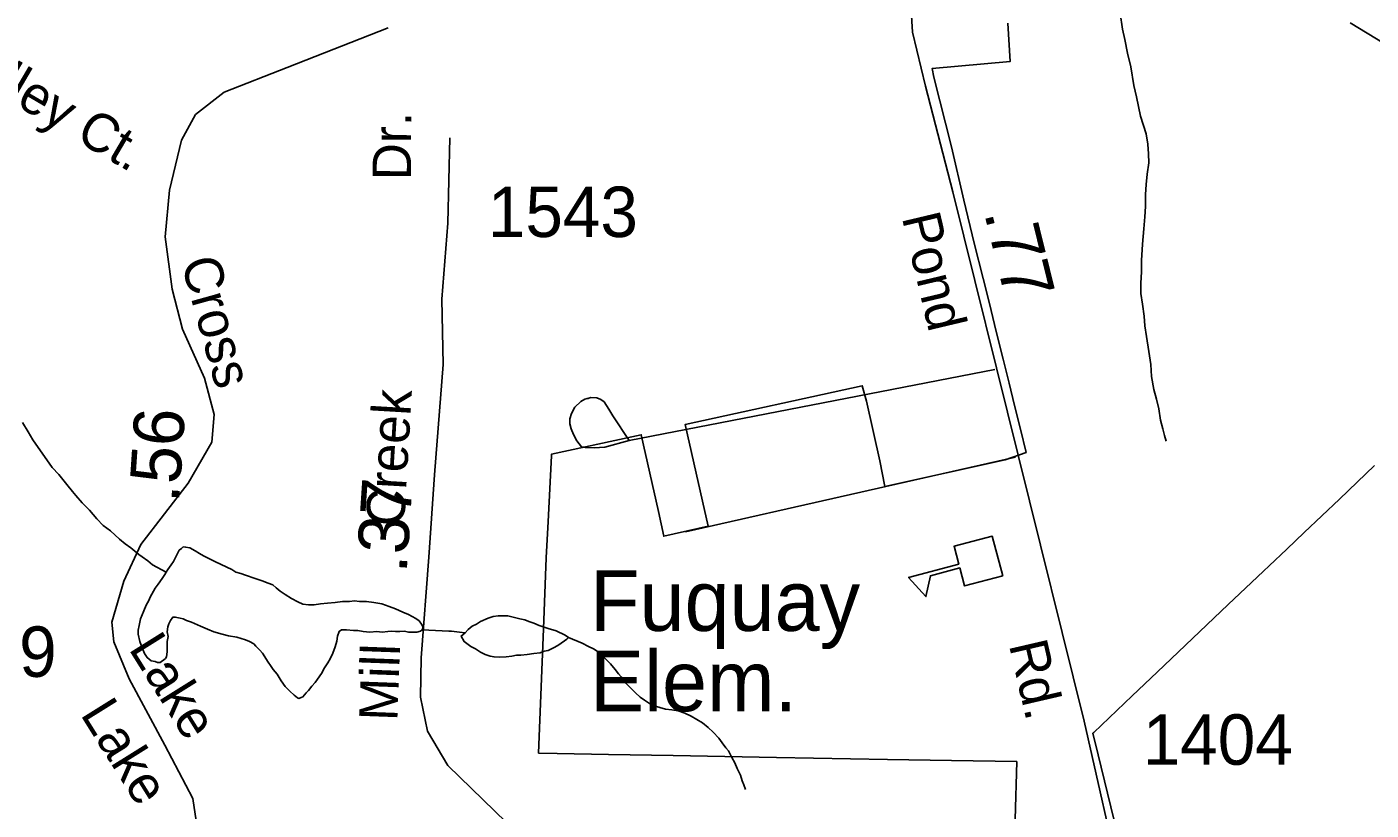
# Model space of a CAD drawing. Extents: x 2001466 to 2224147, y 644118 to 847247.
# Drawn here: x 2069996 to 2073326, y 673987 to 675928 of the extents above; entities that cross this region are included whole.
import ezdxf

# ---------------------------------------------------------------- set-up
doc = ezdxf.new("R2010")
doc.units = 0
for name, color, linetype in [('Exist Boundary Political City Limit New', 7, 'Continuous'), ('Exist Cultural Educational Facility Elementary CELL', 7, 'Continuous'), ('Exist Cultural Educational Facility Elementary Label', 7, 'Continuous'), ('Exist Hydrographic Misc Water Feature', 7, 'Continuous'), ('Exist Road Non-System Type 51', 7, 'Continuous'), ('Exist Road Non-System Type 51 Label', 7, 'Continuous'), ('Exist Road Secondary Mileage Hundredths English Label', 7, 'Continuous'), ('Exist Road Secondary Type 51 Attributed', 7, 'Continuous'), ('Exist Road Secondary Type 51 Label', 7, 'Continuous'), ('Exist Road Secondary Type 51 Number Label', 7, 'Continuous'), ('Map Preparation Boundary City Limit Buffer Line', 7, 'Continuous')]:
    doc.layers.add(name, color=color, linetype=linetype)

msp = doc.modelspace()

# ---------------------------------------------------------------- linework, layer by layer
at = {"layer": 'Exist Boundary Political City Limit New'}
for points in [[(2072426.2, 675937.6), (2072431.8, 675842.2), (2072238.5, 675824.8), (2072242.5, 675803.8), (2072286.8, 675631), (2072317, 675498.6), (2072343.1, 675391.9), (2072365, 675304.7), (2072380.5, 675242.3), (2072397.6, 675173.2), (2072414.5, 675104.6), (2072429.2, 675045.1), (2072443, 674989.8), (2072457.5, 674930.9), (2072471.5, 674873.2), (2072419.2, 674855.2), (2072121.8, 674788.9), (2072109, 674852.2), (2072076, 675000), (2072065.4, 675038.4), (2071626.5, 674942.2), (2071669.6, 674752.2), (2071683.6, 674690.2), (2071573.8, 674665.3), (2071560.5, 674727.1), (2071518.2, 674917.2), (2071494.5, 674911.8), (2071296.1, 674869.2), (2071295.9, 674865.1), (2071287.1, 674701.6), (2071282.2, 674612.2), (2071275.5, 674435.9), (2071263.9, 674127.9), (2071309.8, 674127.1), (2071437.2, 674124.7), (2071597, 674121.8), (2071853.5, 674117.1), (2072127.9, 674112.4), (2072286.5, 674109.7)], [(2073419.4, 675849.8), (2073274.6, 675937.8)], [(2073737, 674256.3), (2073303.4, 673844.5), (2073243.2, 673787.3), (2072727.5, 673804.9), (2072649.8, 674123.6), (2072636.9, 674177.1), (2072639, 674179), (2072734.5, 674270.1), (2072796, 674328.8), (2072866.4, 674395.6), (2072972.1, 674496.1), (2073030.1, 674550.9), (2073059.8, 674579.1), (2073073.6, 674592.2), (2073117.1, 674633.6), (2073160.6, 674674.9), (2073204.1, 674716.2), (2073247.6, 674757.5), (2073291.4, 674799.2), (2073334.9, 674840.6)], [(2072286.5, 674109.7), (2072448.1, 674106.9), (2072440.5, 673819.2)]]:
    msp.add_lwpolyline(points, dxfattribs=at)
at = {"layer": 'Exist Cultural Educational Facility Elementary CELL'}
msp.add_lwpolyline([(2072413.6, 674567.3), (2072319, 674542.3), (2072307.2, 674586.8), (2072234.6, 674567.6), (2072223.2, 674516), (2072180.5, 674563.3), (2072304.7, 674596.1), (2072293, 674640.6), (2072387.7, 674665.6)], close=True, dxfattribs=at)
at = {"layer": 'Exist Hydrographic Misc Water Feature'}
for points in [[(2072818.2, 674901.3), (2072814.3, 674915.2), (2072810, 674931.3), (2072804.5, 674953.2), (2072800.6, 674981), (2072794.4, 675005.1), (2072788.1, 675029.1), (2072782.1, 675061.2), (2072780.3, 675091.1), (2072775.8, 675123.1), (2072769.8, 675160.9), (2072765.9, 675187), (2072764.1, 675210.8), (2072759.8, 675241.1), (2072755.9, 675266.8), (2072755.7, 675293.2), (2072757.7, 675320.9), (2072757.3, 675348.9), (2072759.8, 675389.1), (2072763.4, 675427.1), (2072765.5, 675457.2), (2072767.3, 675482.9), (2072767.1, 675512.9), (2072769, 675537), (2072771.2, 675563), (2072775.1, 675590.8), (2072774.9, 675613.1), (2072773.1, 675637), (2072768.8, 675663.1), (2072754.8, 675707), (2072744.6, 675754.8), (2072738.6, 675782.9), (2072730.6, 675828.8), (2072722.6, 675862.8), (2072716.3, 675896.6), (2072710.5, 675922.6), (2072704.4, 675962.5)], [(2070341.4, 674576.6), (2070307.3, 674594.7), (2070295.4, 674604.6), (2070281.3, 674614.4), (2070273.5, 674620.5), (2070253.6, 674636.5), (2070239.5, 674646.4), (2070225.3, 674658.2), (2070203.2, 674678.6), (2070185.1, 674692.3), (2070169.5, 674708.5), (2070151.1, 674730.3), (2070133.2, 674748), (2070117, 674766.3), (2070109.5, 674776), (2070094.9, 674794), (2070075.2, 674818.1), (2070059, 674835.9), (2070010.8, 674904.1), (2069998.9, 674924.2), (2069985, 674947.7)], [(2070341.4, 674576.6), (2070345.5, 674582.9), (2070353.3, 674594.6), (2070359.4, 674602.6), (2070365.2, 674614.7), (2070369.5, 674622.6), (2070373.4, 674630.9), (2070379.1, 674634.9), (2070383.2, 674638.8), (2070389.1, 674638.7), (2070399.4, 674636.7), (2070413.3, 674628.9), (2070423.4, 674622.9), (2070433.6, 674616.9), (2070461.3, 674603), (2070491.5, 674589.1), (2070503.6, 674582.8), (2070513.6, 674576.8), (2070525.7, 674573), (2070537.8, 674569.1), (2070561.6, 674561), (2070579.2, 674555.1), (2070593.6, 674549.3), (2070605.7, 674545), (2070613.7, 674537.3), (2070623.3, 674529.3), (2070635.6, 674521.4), (2070651.4, 674511.3), (2070667.4, 674503.2), (2070679.7, 674497.3), (2070693.4, 674495.2), (2070707.4, 674495.5), (2070723.6, 674497.6), (2070741.2, 674499.3), (2070759.5, 674501.5), (2070777.7, 674503.6), (2070795.6, 674503.7), (2070807.3, 674505.6), (2070819.8, 674503.7), (2070837.6, 674503.8), (2070855.4, 674501.5), (2070875.7, 674497.6), (2070893.4, 674491.7), (2070909.4, 674485.6), (2070927.6, 674477.6), (2070941.6, 674471.8), (2070959.4, 674461.8), (2070967.8, 674455.7), (2070973.8, 674447.9), (2070977.9, 674439.9), (2070975.6, 674433.8)], [(2070975.6, 674433.8), (2070971.5, 674429.9), (2070961.9, 674427.8), (2070941.4, 674428), (2070931.5, 674429.9), (2070919.6, 674429.7), (2070909.4, 674429.6), (2070899.7, 674429.9), (2070889.9, 674429.7), (2070875.9, 674427.8), (2070863.4, 674429.7), (2070845.8, 674427.5), (2070829.4, 674429.6), (2070815.9, 674431.6), (2070805.6, 674431.6), (2070787.6, 674433.5), (2070775.7, 674433.7), (2070769.5, 674429.7), (2070765.4, 674417.4), (2070763.8, 674405.4), (2070759.9, 674391.4), (2070753.7, 674375.3), (2070747.6, 674361.7), (2070741.6, 674351.6), (2070733.6, 674339.5), (2070725.8, 674325.6), (2070715.8, 674311.3), (2070709.9, 674303.3), (2070701.9, 674293.6), (2070693.9, 674283.4), (2070688.1, 674277.4), (2070680.1, 674267.3), (2070675.8, 674265.5), (2070670.1, 674263.5), (2070666.2, 674265.3), (2070658.2, 674271.4), (2070647.9, 674281.5), (2070635.8, 674293.4), (2070625.8, 674307.1), (2070615.7, 674323.3), (2070605.9, 674335.3), (2070599.9, 674345.1), (2070593.6, 674353.4), (2070579.8, 674375.3), (2070573.5, 674383.2), (2070563.6, 674393.2), (2070557.9, 674398.9), (2070547.9, 674404.9), (2070537.8, 674408.9), (2070515.9, 674415), (2070495.8, 674418.9), (2070479.8, 674423), (2070459.5, 674428.9), (2070443.5, 674434.9), (2070425.9, 674442.9), (2070403.7, 674452.8), (2070391.6, 674457), (2070383.6, 674460.6), (2070375.6, 674462.7), (2070363.5, 674464.9), (2070357.6, 674464.6), (2070351.6, 674456.6), (2070347.7, 674448.6), (2070345.5, 674440.9), (2070343.8, 674428.6), (2070345.9, 674416.9), (2070343.8, 674404.6), (2070343.8, 674392.8), (2070343.6, 674378.7), (2070342.2, 674366.7), (2070339.7, 674362.6), (2070335.6, 674358.8), (2070329.9, 674354.8), (2070326.2, 674352.5), (2070319.8, 674352.7), (2070313.7, 674354.8), (2070303.8, 674356.7), (2070293.8, 674364.7), (2070287.6, 674374.6), (2070281.9, 674388.5), (2070275.8, 674404.8), (2070271.9, 674422.4), (2070271.9, 674432.6), (2070273.9, 674444.4), (2070275.8, 674452.6), (2070277.8, 674460.4), (2070281.7, 674470.8), (2070285.4, 674480.8), (2070291.5, 674494.5), (2070297.9, 674506.5), (2070301.8, 674514.4), (2070313.5, 674536.6), (2070321.5, 674546.7), (2070331.5, 674560.6), (2070337.5, 674570.7), (2070341.4, 674576.6)], [(2071081.8, 674426.2), (2071089.4, 674434), (2071099.5, 674442.2), (2071109.7, 674447.9), (2071119.5, 674454.1), (2071139.2, 674462.1), (2071151.3, 674466.4), (2071163.6, 674468.2), (2071179.4, 674468.2), (2071187.4, 674468.2), (2071217.6, 674460.4), (2071229.5, 674458.2), (2071239.5, 674454.2), (2071251.6, 674450.4), (2071265.5, 674444.2), (2071277.6, 674440.3), (2071287.5, 674436.4), (2071307.4, 674430.6), (2071329.5, 674420.3), (2071337.5, 674414.7)], [(2071081.8, 674426.2), (2071067.7, 674427.9), (2071047.6, 674430.2), (2071041.6, 674429.9), (2070975.6, 674433.8)], [(2071337.5, 674414.7), (2071333.4, 674410.4), (2071313.5, 674396.4), (2071303.7, 674390.6), (2071295.9, 674386.5), (2071287.5, 674382.5), (2071277.8, 674380.3), (2071267.8, 674376.5), (2071251.8, 674374.5), (2071235.6, 674372.5), (2071219.6, 674370.5), (2071209.4, 674370.4), (2071197.7, 674368.5), (2071183.5, 674366.2), (2071167.9, 674366.1), (2071153.4, 674366.3), (2071143.5, 674368.2), (2071131.4, 674372.1), (2071119.8, 674377.9), (2071107.4, 674386.2), (2071095.8, 674392.1), (2071079.4, 674404.3), (2071071.6, 674418), (2071081.8, 674426.2)], [(2071776.1, 674037.5), (2071772.2, 674049.4), (2071767.9, 674059.4), (2071763.8, 674073.4), (2071756, 674089.6), (2071750.1, 674103.4), (2071742.3, 674117.2), (2071733.9, 674133.5), (2071727.9, 674141.3), (2071718.1, 674153.3), (2071709.9, 674165.1), (2071696.2, 674179.4), (2071684.1, 674191.4), (2071669.9, 674203.3), (2071656, 674211), (2071642, 674219.2), (2071625.8, 674226.9), (2071609.8, 674233), (2071594, 674235), (2071577.8, 674237.1), (2071564.1, 674241.2), (2071549.7, 674245), (2071538.1, 674250.8), (2071525.8, 674259.1), (2071515.5, 674266.8), (2071503.6, 674277.1), (2071489.9, 674291), (2071480, 674301), (2071467.9, 674317), (2071462, 674324.8), (2071453.4, 674335), (2071441.7, 674348.9), (2071427.5, 674362.9), (2071419.3, 674370.6), (2071411.3, 674378.7), (2071399.4, 674386.6), (2071387.3, 674392.5), (2071371.8, 674400.5), (2071337.5, 674414.7)]]:
    msp.add_lwpolyline(points, dxfattribs=at)
at = {"layer": 'Exist Road Non-System Type 51'}
for p, q in [((2072393.7, 675078.7), (2071488.1, 674903.1)), ((2072445.3, 674861.6), (2071627.5, 674676.2))]:
    msp.add_line(p, q, dxfattribs=at)
msp.add_lwpolyline([(2071488.1, 674903.1), (2071427.8, 674886.3), (2071401.8, 674884.8), (2071385.8, 674885.2), (2071379.8, 674885.3), (2071369.8, 674887.5), (2071358.1, 674901.7), (2071350.4, 674917.9), (2071344.7, 674932), (2071341, 674944.1), (2071341.2, 674956.1), (2071345.5, 674970), (2071353.8, 674985.8), (2071368.1, 674999.5), (2071378.2, 675005.3), (2071384.2, 675007.2), (2071386.2, 675007.1), (2071392.3, 675009), (2071408.3, 675008.7), (2071418.2, 675004.5), (2071426.1, 674998.3), (2071437.7, 674980.1), (2071447.4, 674963.9), (2071488.1, 674903.1)], dxfattribs=at)
at = {"layer": 'Exist Road Secondary Type 51 Attributed'}
for points in [[(2072367.4, 677776.1), (2072362.4, 677627.2), (2072394, 677399), (2072419.2, 677268), (2072420.8, 677193.7), (2072412.9, 677071.4), (2072376.6, 676885), (2072308.8, 676591.3), (2072253.5, 676367.9), (2072209.3, 676153.1), (2072184.1, 676011), (2072190.4, 675914.7), (2072222, 675781.3), (2072289.8, 675519.2), (2072614.9, 674207), (2072710.3, 673786.9)], [(2070415.2, 673959.8), (2070407.3, 674015.1), (2070337.9, 674147.7), (2070249.5, 674312), (2070211.7, 674403.6), (2070206.9, 674452.5), (2070236.1, 674554), (2070278.7, 674644.8), (2070395.5, 674797.1), (2070453.9, 674898.6), (2070460.2, 674967.3), (2070436.5, 675057.3), (2070381.3, 675178.9), (2070356.1, 675278.3), (2070338.7, 675407.8), (2070349, 675523.5), (2070378.9, 675647.5), (2070413.6, 675710.6), (2070484.7, 675765.9), (2070640.9, 675827.5), (2070891.1, 675925.5)], [(2071317, 673839), (2071212.9, 673927.9), (2071039.3, 674096.8), (2070988.8, 674182.5), (2070971.4, 674266.2), (2070973, 674364.1), (2070992, 674613.6), (2071006.2, 674817.7), (2071027.5, 675090.8), (2071024.3, 675253.5), (2071039.3, 675441.8), (2071043.6, 675653)]]:
    msp.add_lwpolyline(points, dxfattribs=at)
at = {"layer": 'Map Preparation Boundary City Limit Buffer Line'}
for points in [[(2072426.2, 675937.6), (2072431.8, 675842.2), (2072238.5, 675824.8), (2072242.5, 675803.8), (2072286.8, 675631), (2072317, 675498.6), (2072343.1, 675391.9), (2072365, 675304.7), (2072380.5, 675242.3), (2072397.6, 675173.2), (2072414.5, 675104.6), (2072429.2, 675045.1), (2072443, 674989.8), (2072457.5, 674930.9), (2072471.5, 674873.2), (2072419.2, 674855.2), (2072121.8, 674788.9), (2072109, 674852.2), (2072076, 675000), (2072065.4, 675038.4), (2071626.5, 674942.2), (2071669.6, 674752.2), (2071683.6, 674690.2), (2071573.8, 674665.3), (2071560.5, 674727.1), (2071518.2, 674917.2), (2071494.5, 674911.8), (2071296.1, 674869.2), (2071295.9, 674865.1), (2071287.1, 674701.6), (2071282.2, 674612.2), (2071275.5, 674435.9), (2071263.9, 674127.9), (2071309.8, 674127.1), (2071437.2, 674124.7), (2071597, 674121.8), (2071853.5, 674117.1), (2072127.9, 674112.4), (2072286.5, 674109.7)], [(2073419.4, 675849.8), (2073274.6, 675937.8)], [(2073737, 674256.3), (2073303.4, 673844.5), (2073243.2, 673787.3), (2072727.5, 673804.9), (2072649.8, 674123.6), (2072636.9, 674177.1), (2072639, 674179), (2072734.5, 674270.1), (2072796, 674328.8), (2072866.4, 674395.6), (2072972.1, 674496.1), (2073030.1, 674550.9), (2073059.8, 674579.1), (2073073.6, 674592.2), (2073117.1, 674633.6), (2073160.6, 674674.9), (2073204.1, 674716.2), (2073247.6, 674757.5), (2073291.4, 674799.2), (2073334.9, 674840.6)], [(2072286.5, 674109.7), (2072448.1, 674106.9), (2072440.5, 673819.2)]]:
    msp.add_lwpolyline(points, dxfattribs=at)

# ---------------------------------------------------------------- texts
at = {"layer": 'Exist Cultural Educational Facility Elementary Label'}
for s, p in [('Fuquay', (2071391.2, 674430.8)), ('Elem.', (2071391.2, 674231.6))]:
    msp.add_text(s, height=150, dxfattribs=at).set_placement(p)
at = {"layer": 'Exist Road Non-System Type 51 Label'}
msp.add_text('Stone Valley Ct.', height=95, rotation=329.6196, dxfattribs=at).set_placement((2069467.4, 676027.3))
at = {"layer": 'Exist Road Secondary Mileage Hundredths English Label'}
for s, rotation, p in [('.77', 283.9132, (2072367, 675467.4)), ('.56', 86.2228, (2070372.9, 674746.6)), ('.37', 86.2228, (2070936.7, 674572.5))]:
    msp.add_text(s, height=125, rotation=rotation, dxfattribs=at).set_placement(p)
at = {"layer": 'Exist Road Secondary Type 51 Label'}
for s, rotation, p in [('Dr.', 89.7083, (2070947.5, 675547.9)), ('Pond', 283.3682, (2072163.2, 675456.3)), ('Cross', 285.5182, (2070377.3, 675345.4)), ('Creek', 86.635, (2070930.1, 674688.2)), ('Lake', 301.9947, (2070246.7, 674386.9)), ('Rd.', 283.0495, (2072428.5, 674396.8)), ('Mill', 87.8797, (2070913.7, 674206.5)), ('Lake', 301.9947, (2070127, 674224.4))]:
    msp.add_text(s, height=95, rotation=rotation, dxfattribs=at).set_placement(p)
at = {"layer": 'Exist Road Secondary Type 51 Number Label'}
for s, p in [('1543', (2071138, 675407.2)), ('4749', (2069698, 674316.9)), ('1404', (2072760.3, 674099))]:
    msp.add_text(s, height=125, dxfattribs=at).set_placement(p)

doc.saveas('drawing.dxf')
